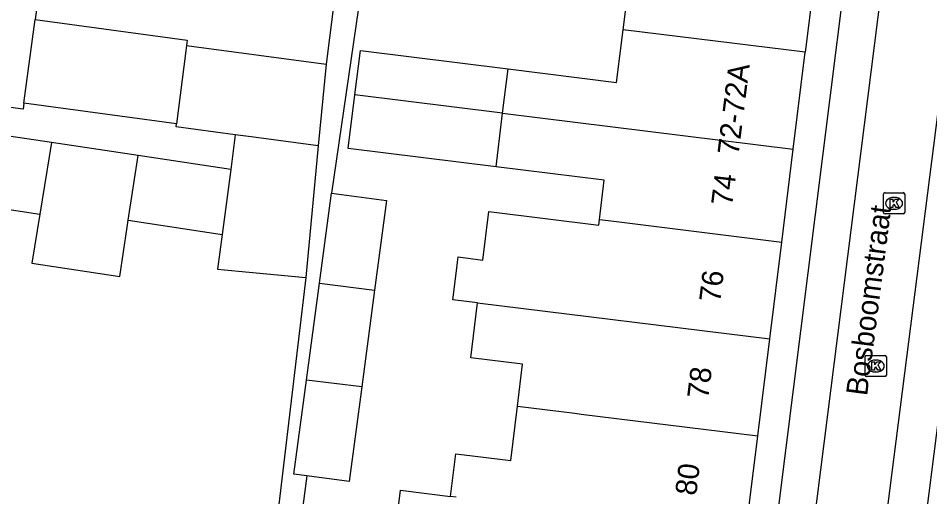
# Model space of a CAD drawing. Extents: x 162172 to 163187, y 382874 to 383684.
# Drawn here: x 162685.16 to 162728.02, y 383348.92 to 383371.43 of the extents above; entities that cross this region are included whole.
import ezdxf

# ---------------------------------------------------------------- set-up
doc = ezdxf.new("R2010")
doc.units = 0
for name, color, linetype in [('IMGEO_Kolk', 7, 'Continuous'), ('IMGEO_Openbare_ruimte_label', 7, 'Continuous'), ('IMGEO_Pand', 7, 'Continuous'), ('IMGEO_Pand_nummerreeks', 7, 'Continuous'), ('IMGEO_Parkeervlak_open', 7, 'Continuous'), ('IMGEO_Voetpad_open', 7, 'Continuous')]:
    doc.layers.add(name, color=color, linetype=linetype)

msp = doc.modelspace()

# ---------------------------------------------------------------- linework, layer by layer
at = {"layer": 'IMGEO_Kolk'}
for p, q in [((162725.839, 383362.298), (162725.839, 383363.15)), ((162725.914, 383363.224), (162726.766, 383363.224)), ((162726.84, 383363.15), (162726.84, 383362.298)), ((162726.327, 383363.004), (162726.352, 383363.004)), ((162726.766, 383362.224), (162725.914, 383362.224)), ((162726.35, 383362.444), (162726.325, 383362.444)), ((162724.977, 383354.644), (162724.977, 383355.496)), ((162725.052, 383355.57), (162725.904, 383355.57)), ((162725.465, 383355.35), (162725.49, 383355.35)), ((162725.978, 383355.496), (162725.978, 383354.644)), ((162725.904, 383354.57), (162725.052, 383354.57)), ((162725.488, 383354.79), (162725.463, 383354.79))]:
    msp.add_line(p, q, dxfattribs=at)
for points in [[(162725.839, 383362.298), (162725.839, 383363.15)], [(162725.914, 383363.224), (162726.766, 383363.224)], [(162726.84, 383363.15), (162726.84, 383362.298)], [(162726.16, 383362.924), (162726.283, 383362.924), (162726.283, 383362.773), (162726.413, 383362.924), (162726.577, 383362.924), (162726.431, 383362.773), (162726.584, 383362.524), (162726.432, 383362.524), (162726.347, 383362.688), (162726.283, 383362.621), (162726.283, 383362.524), (162726.16, 383362.524), (162726.16, 383362.924)], [(162726.766, 383362.224), (162725.914, 383362.224)], [(162724.977, 383354.644), (162724.977, 383355.496)], [(162725.052, 383355.57), (162725.904, 383355.57)], [(162725.978, 383355.496), (162725.978, 383354.644)], [(162725.298, 383355.27), (162725.421, 383355.27), (162725.421, 383355.119), (162725.551, 383355.27), (162725.715, 383355.27), (162725.569, 383355.119), (162725.722, 383354.87), (162725.57, 383354.87), (162725.485, 383355.034), (162725.421, 383354.967), (162725.421, 383354.87), (162725.298, 383354.87), (162725.298, 383355.27)], [(162725.904, 383354.57), (162725.052, 383354.57)]]:
    msp.add_lwpolyline(points, dxfattribs=at)
for centre, start, end in [((162725.916, 383363.148), 91.552, 178.448), ((162725.916, 383363.148), 91.552, 178.448), ((162726.764, 383363.148), 1.552, 88.448), ((162726.764, 383363.148), 1.552, 88.448), ((162725.916, 383362.3), 181.552, 268.448), ((162725.916, 383362.3), 181.552, 268.448), ((162726.764, 383362.3), 271.552, 358.448), ((162726.764, 383362.3), 271.552, 358.448), ((162725.054, 383355.494), 91.552, 178.448), ((162725.054, 383355.494), 91.552, 178.448), ((162725.902, 383355.494), 1.552, 88.448), ((162725.902, 383355.494), 1.552, 88.448), ((162725.054, 383354.646), 181.552, 268.448), ((162725.054, 383354.646), 181.552, 268.448), ((162725.902, 383354.646), 271.552, 358.448), ((162725.902, 383354.646), 271.552, 358.448)]:
    msp.add_arc(centre, 0.0765, start, end, dxfattribs=at)
for centre, major_axis, ratio, start_param, end_param in [((162726.326, 383362.724), (-0.387, 0.002), 0.722429, 4.712389, 7.853982), ((162726.351, 383362.724), (-0.39, 0.002), 0.717154, 1.570796, 4.712389), ((162725.464, 383355.07), (-0.387, 0.002), 0.722429, 4.712389, 7.853982), ((162725.489, 383355.07), (-0.39, 0.002), 0.717154, 1.570796, 4.712389)]:
    msp.add_ellipse(centre, major_axis=major_axis, ratio=ratio, start_param=start_param, end_param=end_param, dxfattribs=at)
at = {"layer": 'IMGEO_Pand'}
for points in [[(162713.603, 383370.889), (162713.849, 383372.875), (162708.785, 383373.503), (162709.128, 383376.278)], [(162685.425, 383367.428), (162685.388, 383367.153), (162675.713, 383368.44), (162676.707, 383375.803), (162686.382, 383374.516), (162685.957, 383371.365)], [(162722.755, 383374.589), (162722.165, 383369.828)], [(162685.425, 383367.428), (162685.957, 383371.365)], [(162685.957, 383371.365), (162693.103, 383370.401), (162693.069, 383370.149)], [(162708.196, 383369.046), (162713.296, 383368.414), (162713.603, 383370.889)], [(162722.165, 383369.828), (162713.603, 383370.889)], [(162693.069, 383370.149), (162693.035, 383369.894), (162692.61, 383366.459)], [(162693.069, 383370.149), (162699.635, 383369.263)], [(162700.991, 383367.821), (162701.249, 383369.907), (162708.196, 383369.046)], [(162721.6, 383365.266), (162722.165, 383369.828)], [(162699.635, 383369.263), (162699.269, 383365.427)], [(162707.937, 383366.96), (162708.196, 383369.046)], [(162707.625, 383364.439), (162700.678, 383365.299), (162700.991, 383367.821)], [(162707.937, 383366.96), (162700.991, 383367.821)], [(162692.61, 383366.459), (162685.425, 383367.428)], [(162707.625, 383364.439), (162707.937, 383366.96)], [(162707.937, 383366.96), (162721.6, 383365.266)], [(162686.722, 383365.581), (162682.173, 383366.265), (162681.666, 383362.897), (162686.176, 383362.219)], [(162695.367, 383365.95), (162692.593, 383366.322), (162692.61, 383366.459)], [(162695.367, 383365.95), (162695.15, 383364.314)], [(162699.269, 383365.427), (162696.118, 383365.849), (162695.367, 383365.95)], [(162686.722, 383365.581), (162686.176, 383362.219)], [(162690.793, 383364.969), (162686.722, 383365.581)], [(162699.269, 383365.427), (162698.677, 383359.232)], [(162721.059, 383360.903), (162721.6, 383365.266)], [(162690.335, 383361.927), (162690.793, 383364.969)], [(162695.15, 383364.314), (162690.793, 383364.969)], [(162712.484, 383361.966), (162712.712, 383363.809), (162707.625, 383364.439)], [(162695.15, 383364.314), (162694.745, 383361.264)], [(162699.324, 383358.966), (162699.889, 383363.201)], [(162699.889, 383363.201), (162702.479, 383362.855), (162701.917, 383358.645)], [(162686.176, 383362.219), (162685.799, 383359.901), (162689.937, 383359.278), (162690.286, 383361.6), (162690.335, 383361.927)], [(162706.76, 383358.044), (162705.602, 383358.188), (162705.785, 383359.67), (162705.821, 383359.956), (162705.851, 383360.2), (162707.009, 383360.056), (162707.292, 383362.341), (162712.451, 383361.701), (162712.484, 383361.966)], [(162690.335, 383361.927), (162694.745, 383361.264)], [(162712.484, 383361.966), (162713.166, 383361.881), (162721.059, 383360.903)], [(162694.745, 383361.264), (162694.528, 383359.628), (162695.514, 383359.534), (162698.677, 383359.232)], [(162720.493, 383356.341), (162721.059, 383360.903)], [(162698.716, 383354.41), (162699.324, 383358.966)], [(162699.324, 383358.966), (162701.917, 383358.645)], [(162701.917, 383358.645), (162701.309, 383354.088)], [(162708.631, 383353.18), (162708.876, 383355.15), (162706.439, 383355.452), (162706.76, 383358.044)], [(162706.76, 383358.044), (162720.493, 383356.341)], [(162719.928, 383351.779), (162720.493, 383356.341)], [(162698.724, 383349.905), (162698.125, 383349.985), (162698.716, 383354.41)], [(162701.309, 383354.088), (162698.716, 383354.41)], [(162701.309, 383354.088), (162700.716, 383349.639), (162698.724, 383349.905)], [(162705.482, 383348.935), (162705.729, 383350.939), (162706, 383350.905), (162708.314, 383350.618), (162708.631, 383353.18)], [(162708.631, 383353.18), (162711.332, 383352.845), (162711.627, 383352.808), (162719.928, 383351.779)], [(162719.362, 383347.217), (162719.367, 383347.259), (162719.928, 383351.779)], [(162705.449, 383346.46), (162702.837, 383346.784), (162703.139, 383349.225), (162705.482, 383348.935)], [(162705.752, 383348.902), (162705.482, 383348.935)]]:
    msp.add_lwpolyline(points, dxfattribs=at)
at = {"layer": 'IMGEO_Parkeervlak_open'}
for points in [[(162728.889, 383397.652), (162721.945, 383342.755)], [(162725.256, 383342.312), (162732.253, 383397.166)]]:
    msp.add_lwpolyline(points, dxfattribs=at)
at = {"layer": 'IMGEO_Voetpad_open'}
for points in [[(162702.846, 383401.116), (162703.655, 383401.01), (162699.635, 383369.263)], [(162721.945, 383342.755), (162720.225, 383342.985), (162727.106, 383397.755)], [(162732.253, 383397.166), (162734.046, 383396.932), (162727.077, 383342.068), (162725.256, 383342.312)], [(162701.266, 383372.681), (162699.889, 383363.201)], [(162698.677, 383359.232), (162696.946, 383344.607)], [(162698.724, 383349.905), (162698.085, 383345.025)]]:
    msp.add_lwpolyline(points, dxfattribs=at)

# ---------------------------------------------------------------- texts
at = {"layer": 'IMGEO_Openbare_ruimte_label'}
msp.add_text('Bosboomstraat', height=1, rotation=82.7044, dxfattribs=at).set_placement((162725.068, 383353.634))
at = {"layer": 'IMGEO_Pand_nummerreeks'}
for s, rotation, p in [('72-72A', 82.8871, (162719.023, 383364.96)), ('74', 82.9299, (162718.725, 383362.574)), ('76', 82.9299, (162718.161, 383358.03)), ('78', 82.9299, (162717.598, 383353.489)), ('80', 82.9299, (162717.034, 383348.945))]:
    msp.add_text(s, height=1, rotation=rotation, dxfattribs=at).set_placement(p)

doc.saveas('drawing.dxf')
